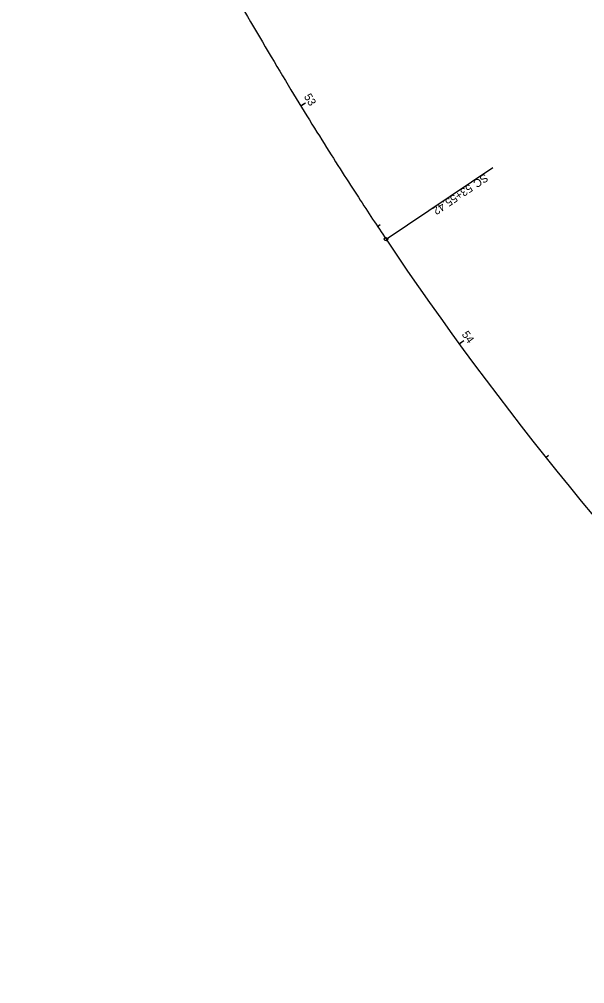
# Model space of a CAD drawing. Extents: x 1492452 to 1496782, y 514026 to 517659.
# Drawn here: x 1494344.2 to 1494541.8, y 514788.1 to 515125.3 of the extents above; entities that cross this region are included whole.
import ezdxf

# ---------------------------------------------------------------- set-up
doc = ezdxf.new("R2010")
doc.units = 0
for name, color, linetype in [('Default', 7, 'Continuous'), ('GE_X_Cells', 7, 'Continuous'), ('PV_X_EOP', 7, 'Continuous'), ('PV_X_Shoulder_Aggregate', 7, 'Continuous'), ('RD_X_GR_Rt', 7, 'Continuous'), ('RD_X_Wall', 7, 'Continuous'), ('SV_X_Top_of_Bank', 7, 'Continuous'), ('XS_X_Ground_Line', 7, 'Continuous')]:
    doc.layers.add(name, color=color, linetype=linetype)

msp = doc.modelspace()

# ---------------------------------------------------------------- linework, layer by layer
at = {"layer": 'Default'}
msp.add_arc((1486425.91, 524780.42), 12277.67, 302.444021, 313.600151, dxfattribs=at)
at = {"layer": 'GE_X_Cells'}
msp.add_arc((1486425.91, 524780.42), 12277.67, 302.444021, 313.600151, dxfattribs=at)
at = {"layer": 'PV_X_EOP'}
msp.add_line((1494472.4, 515048.36), (1494509.78, 515073.41), dxfattribs=at)
msp.add_circle((1494472.4, 515048.36), 0.6, dxfattribs=at)
at = {"layer": 'PV_X_Shoulder_Aggregate'}
for p, q in [((1494442.57, 515095.05), (1494444.28, 515096.09)), ((1494469.4, 515052.86), (1494470.4, 515053.52)), ((1494497.94, 515011.81), (1494499.56, 515012.99)), ((1494528.24, 514972.05), (1494529.18, 514972.8))]:
    msp.add_line(p, q, dxfattribs=at)
at = {"layer": 'RD_X_GR_Rt'}
msp.add_line((1494472.4, 515048.36), (1494509.78, 515073.41), dxfattribs=at)
msp.add_circle((1494472.4, 515048.36), 0.6, dxfattribs=at)
at = {"layer": 'RD_X_Wall'}
for p, q in [((1494442.57, 515095.05), (1494443.59, 515095.68)), ((1494497.94, 515011.81), (1494498.91, 515012.52))]:
    msp.add_line(p, q, dxfattribs=at)
at = {"layer": 'SV_X_Top_of_Bank'}
msp.add_arc((1495424.3, 515686.35), 1145.92, 213.83122, 224.58118, dxfattribs=at)
msp.add_arc((1495424.3, 515686.35), 1145.92, 213.83122, 224.58118, dxfattribs=at)
msp.add_open_spline([(1494370.94, 515220.63), (1494373.62, 515215.76), (1494378.97, 515206.03), (1494389.71, 515186.57), (1494403.23, 515162.3), (1494419.72, 515133.34), (1494436.64, 515104.61), (1494451.2, 515080.96), (1494463.19, 515062.25), (1494469.31, 515052.97), (1494472.4, 515048.36)], degree=3, dxfattribs=at)
msp.add_open_spline([(1494370.94, 515220.63), (1494373.62, 515215.76), (1494378.97, 515206.03), (1494389.71, 515186.57), (1494403.23, 515162.3), (1494419.72, 515133.34), (1494436.64, 515104.61), (1494451.2, 515080.96), (1494463.19, 515062.25), (1494469.31, 515052.97), (1494472.4, 515048.36)], degree=3, dxfattribs=at)
at = {"layer": 'XS_X_Ground_Line'}
msp.add_line((1494472.4, 515048.36), (1494509.78, 515073.41), dxfattribs=at)
msp.add_circle((1494472.4, 515048.36), 0.6, dxfattribs=at)

# ---------------------------------------------------------------- texts
at = {"layer": 'PV_X_EOP'}
for s, p in [('SC', (1494506.89, 515071.41)), ('53+55.42', (1494501.47, 515067.78))]:
    msp.add_text(s, height=2.8, rotation=213.8312, dxfattribs=at).set_placement(p)
at = {"layer": 'PV_X_Shoulder_Aggregate'}
for s, rotation, p in [('53', 301.4443, (1494443.61, 515098.24)), ('54', 306.0605, (1494498.73, 515015.05))]:
    msp.add_text(s, height=2.8, rotation=rotation, dxfattribs=at).set_placement(p)
at = {"layer": 'RD_X_GR_Rt'}
for s, p in [('SC', (1494506.89, 515071.41)), ('53+55.42', (1494501.47, 515067.78))]:
    msp.add_text(s, height=2.8, rotation=213.8312, dxfattribs=at).set_placement(p)
at = {"layer": 'XS_X_Ground_Line'}
for s, p in [('SC', (1494506.89, 515071.41)), ('53+55.42', (1494501.47, 515067.78))]:
    msp.add_text(s, height=2.8, rotation=213.8312, dxfattribs=at).set_placement(p)

doc.saveas('drawing.dxf')
